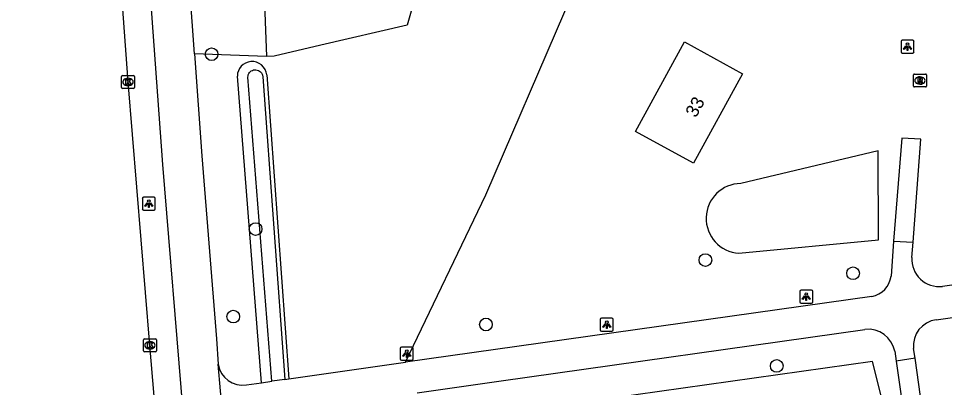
# Model space of a CAD drawing. Extents: x 159451 to 160663, y 388402 to 389723.
# Drawn here: x 159455.9 to 159527.4, y 389293.3 to 389321.7 of the extents above; entities that cross this region are included whole.
import ezdxf

# ---------------------------------------------------------------- set-up
doc = ezdxf.new("R2010")
doc.units = 0
for name, color, linetype in [('IMGEO_Boom', 7, 'Continuous'), ('IMGEO_Fietspad_gesloten', 7, 'Continuous'), ('IMGEO_Greppel_droge_sloot', 7, 'Continuous'), ('IMGEO_Kolk', 7, 'Continuous'), ('IMGEO_Lichtpunt', 7, 'Continuous'), ('IMGEO_Loofbos', 7, 'Continuous'), ('IMGEO_Meer_plas_ven_vijver', 7, 'Continuous'), ('IMGEO_Pand', 7, 'Continuous'), ('IMGEO_Pand_nummerreeks', 7, 'Continuous'), ('IMGEO_Rijbaan_lokaal_gesloten', 7, 'Continuous'), ('IMGEO_Rijbaan_regionaal_gesloten', 7, 'Continuous'), ('IMGEO_Rioolput', 7, 'Continuous')]:
    doc.layers.add(name, color=color, linetype=linetype)

msp = doc.modelspace()

# ---------------------------------------------------------------- linework, layer by layer
at = {"layer": 'IMGEO_Boom'}
for centre in [(159470.842, 389318.982), (159474.232, 389305.486), (159508.939, 389303.101), (159520.344, 389302.083), (159472.511, 389298.735), (159492.013, 389298.126), (159514.448, 389294.93)]:
    msp.add_circle(centre, 0.489, dxfattribs=at)
at = {"layer": 'IMGEO_Fietspad_gesloten'}
for points in [[(159469.519, 389319.015), (159468.808, 389329.001), (159467.416, 389348.979), (159465.554, 389376.915), (159464.112, 389404.118), (159462.376, 389437.214), (159460.98, 389466.613), (159459.958, 389496.642), (159459.465, 389512.981), (159459.166, 389522.863), (159459.08, 389525.773)], [(159455.942, 389525.002), (159456.038, 389522.126), (159456.372, 389512.313), (159456.916, 389496.35), (159457.955, 389465.071), (159459.294, 389436.93), (159461.071, 389403.687), (159462.508, 389376.402), (159464.342, 389348.5), (159465.649, 389329.916), (159467.063, 389310.472), (159468.609, 389291.384), (159470.151, 389272.51), (159471.683, 389255.143), (159473.293, 389238.955), (159476.115, 389210.723), (159476.688, 389204.954), (159478.244, 389191.231), (159479.81, 389178.066)], [(159469.519, 389319.015), (159470.079, 389311.141), (159471.221, 389297.013), (159471.345, 389295.068)]]:
    msp.add_lwpolyline(points, dxfattribs=at)
at = {"layer": 'IMGEO_Greppel_droge_sloot'}
msp.add_lwpolyline([(159475.498, 389293.751), (159473.642, 389317.216), (159473.65, 389317.307), (159473.674, 389317.398), (159473.713, 389317.483), (159473.764, 389317.561), (159473.828, 389317.63), (159473.902, 389317.688), (159473.985, 389317.732), (159474.073, 389317.763), (159474.163, 389317.779), (159474.265, 389317.779), (159474.364, 389317.761), (159474.459, 389317.727), (159474.546, 389317.676), (159474.624, 389317.611), (159474.688, 389317.534), (159474.739, 389317.447), (159474.773, 389317.352), (159474.794, 389317.233), (159476.493, 389293.892)], dxfattribs=at)
at = {"layer": 'IMGEO_Kolk'}
for p, q in [((159463.891, 389316.417), (159463.891, 389317.269)), ((159463.966, 389317.343), (159464.818, 389317.343)), ((159464.379, 389317.123), (159464.404, 389317.123)), ((159464.892, 389317.269), (159464.892, 389316.417)), ((159464.818, 389316.343), (159463.966, 389316.343)), ((159464.402, 389316.563), (159464.377, 389316.563)), ((159465.58, 389296.099), (159465.58, 389296.951)), ((159465.655, 389297.025), (159466.507, 389297.025)), ((159466.068, 389296.805), (159466.093, 389296.805)), ((159466.581, 389296.951), (159466.581, 389296.099)), ((159466.091, 389296.245), (159466.066, 389296.245)), ((159466.507, 389296.025), (159465.655, 389296.025))]:
    msp.add_line(p, q, dxfattribs=at)
for points in [[(159463.891, 389316.417), (159463.891, 389317.269)], [(159463.966, 389317.343), (159464.818, 389317.343)], [(159464.212, 389317.043), (159464.335, 389317.043), (159464.335, 389316.892), (159464.465, 389317.043), (159464.629, 389317.043), (159464.483, 389316.892), (159464.636, 389316.643), (159464.484, 389316.643), (159464.399, 389316.807), (159464.335, 389316.74), (159464.335, 389316.643), (159464.212, 389316.643), (159464.212, 389317.043)], [(159464.892, 389317.269), (159464.892, 389316.417)], [(159464.818, 389316.343), (159463.966, 389316.343)], [(159465.58, 389296.099), (159465.58, 389296.951)], [(159465.655, 389297.025), (159466.507, 389297.025)], [(159466.581, 389296.951), (159466.581, 389296.099)], [(159465.901, 389296.725), (159466.024, 389296.725), (159466.024, 389296.574), (159466.154, 389296.725), (159466.318, 389296.725), (159466.172, 389296.574), (159466.325, 389296.325), (159466.173, 389296.325), (159466.088, 389296.489), (159466.024, 389296.422), (159466.024, 389296.325), (159465.901, 389296.325), (159465.901, 389296.725)], [(159466.507, 389296.025), (159465.655, 389296.025)]]:
    msp.add_lwpolyline(points, dxfattribs=at)
for centre, start, end in [((159463.968, 389317.267), 91.55205, 178.44795), ((159463.968, 389317.267), 91.55205, 178.44795), ((159464.816, 389317.267), 1.55205, 88.44795), ((159464.816, 389317.267), 1.55205, 88.44795), ((159463.968, 389316.419), 181.55205, 268.44795), ((159463.968, 389316.419), 181.55205, 268.44795), ((159464.816, 389316.419), 271.55205, 358.44795), ((159464.816, 389316.419), 271.55205, 358.44795), ((159465.657, 389296.949), 91.55205, 178.44795), ((159465.657, 389296.949), 91.55205, 178.44795), ((159466.505, 389296.949), 1.55205, 88.44795), ((159466.505, 389296.949), 1.55205, 88.44795), ((159465.657, 389296.101), 181.55205, 268.44795), ((159465.657, 389296.101), 181.55205, 268.44795), ((159466.505, 389296.101), 271.55205, 358.44795), ((159466.505, 389296.101), 271.55205, 358.44795)]:
    msp.add_arc(centre, 0.0765, start, end, dxfattribs=at)
for centre, major_axis, ratio, start_param, end_param in [((159464.378, 389316.843), (-0.387, 0.002), 0.722429, 4.712389, 7.853982), ((159464.403, 389316.843), (-0.39, 0.002), 0.717154, 1.570796, 4.712389), ((159466.067, 389296.525), (-0.387, 0.002), 0.722429, 4.712389, 7.853982), ((159466.092, 389296.525), (-0.39, 0.002), 0.717154, 1.570796, 4.712389)]:
    msp.add_ellipse(centre, major_axis=major_axis, ratio=ratio, start_param=start_param, end_param=end_param, dxfattribs=at)
at = {"layer": 'IMGEO_Lichtpunt'}
for p, q in [((159524.044, 389319.966), (159524.044, 389319.159)), ((159524.044, 389319.966), (159524.044, 389319.159)), ((159524.946, 389320.061), (159524.138, 389320.061)), ((159524.946, 389320.061), (159524.138, 389320.061)), ((159525.04, 389319.159), (159525.04, 389319.966)), ((159525.04, 389319.159), (159525.04, 389319.966)), ((159524.138, 389319.065), (159524.946, 389319.065)), ((159524.138, 389319.065), (159524.946, 389319.065)), ((159465.496, 389307.856), (159465.496, 389307.049)), ((159465.496, 389307.856), (159465.496, 389307.049)), ((159466.398, 389307.951), (159465.59, 389307.951)), ((159466.398, 389307.951), (159465.59, 389307.951)), ((159466.492, 389307.049), (159466.492, 389307.856)), ((159466.492, 389307.049), (159466.492, 389307.856)), ((159465.59, 389306.955), (159466.398, 389306.955)), ((159465.59, 389306.955), (159466.398, 389306.955)), ((159516.229, 389300.684), (159516.229, 389299.877)), ((159516.229, 389300.684), (159516.229, 389299.877)), ((159517.131, 389300.779), (159516.323, 389300.779)), ((159517.131, 389300.779), (159516.323, 389300.779)), ((159517.225, 389299.877), (159517.225, 389300.684)), ((159517.225, 389299.877), (159517.225, 389300.684)), ((159516.323, 389299.783), (159517.131, 389299.783)), ((159516.323, 389299.783), (159517.131, 389299.783)), ((159500.834, 389298.511), (159500.834, 389297.704)), ((159500.834, 389298.511), (159500.834, 389297.704)), ((159501.736, 389298.606), (159500.928, 389298.606)), ((159501.736, 389298.606), (159500.928, 389298.606)), ((159501.83, 389297.704), (159501.83, 389298.511)), ((159501.83, 389297.704), (159501.83, 389298.511)), ((159500.928, 389297.61), (159501.736, 389297.61)), ((159500.928, 389297.61), (159501.736, 389297.61)), ((159485.399, 389296.277), (159485.399, 389295.47)), ((159485.399, 389296.277), (159485.399, 389295.47)), ((159486.301, 389296.372), (159485.493, 389296.372)), ((159486.301, 389296.372), (159485.493, 389296.372)), ((159486.395, 389295.47), (159486.395, 389296.277)), ((159486.395, 389295.47), (159486.395, 389296.277)), ((159485.493, 389295.376), (159486.301, 389295.376)), ((159485.493, 389295.376), (159486.301, 389295.376))]:
    msp.add_line(p, q, dxfattribs=at)
for points in [[(159524.418, 389319.63), (159524.457, 389319.602), (159524.269, 389319.34), (159524.231, 389319.367), (159524.418, 389319.63)], [(159524.63, 389319.602), (159524.668, 389319.629), (159524.855, 389319.367), (159524.816, 389319.339), (159524.63, 389319.602)], [(159524.52, 389319.582), (159524.567, 389319.582), (159524.567, 389319.26), (159524.52, 389319.26), (159524.52, 389319.582)], [(159465.87, 389307.52), (159465.909, 389307.492), (159465.721, 389307.23), (159465.683, 389307.257), (159465.87, 389307.52)], [(159465.972, 389307.472), (159466.019, 389307.472), (159466.019, 389307.15), (159465.972, 389307.15), (159465.972, 389307.472)], [(159466.082, 389307.492), (159466.12, 389307.519), (159466.307, 389307.257), (159466.268, 389307.229), (159466.082, 389307.492)], [(159516.603, 389300.348), (159516.642, 389300.32), (159516.454, 389300.058), (159516.416, 389300.085), (159516.603, 389300.348)], [(159516.815, 389300.32), (159516.853, 389300.347), (159517.04, 389300.085), (159517.001, 389300.057), (159516.815, 389300.32)], [(159516.705, 389300.3), (159516.752, 389300.3), (159516.752, 389299.978), (159516.705, 389299.978), (159516.705, 389300.3)], [(159501.208, 389298.175), (159501.247, 389298.147), (159501.059, 389297.885), (159501.021, 389297.912), (159501.208, 389298.175)], [(159501.31, 389298.127), (159501.357, 389298.127), (159501.357, 389297.805), (159501.31, 389297.805), (159501.31, 389298.127)], [(159501.42, 389298.147), (159501.458, 389298.174), (159501.645, 389297.912), (159501.606, 389297.884), (159501.42, 389298.147)], [(159485.773, 389295.941), (159485.812, 389295.913), (159485.624, 389295.651), (159485.586, 389295.678), (159485.773, 389295.941)], [(159485.875, 389295.893), (159485.922, 389295.893), (159485.922, 389295.571), (159485.875, 389295.571), (159485.875, 389295.893)], [(159485.985, 389295.913), (159486.023, 389295.94), (159486.21, 389295.678), (159486.171, 389295.65), (159485.985, 389295.913)]]:
    msp.add_lwpolyline(points, dxfattribs=at)
for centre in [(159524.543, 389319.764), (159465.995, 389307.654), (159516.728, 389300.482), (159501.333, 389298.309), (159485.898, 389296.075)]:
    msp.add_circle(centre, 0.0994, dxfattribs=at)
for centre, start, end in [((159524.138, 389319.966), 90, 180), ((159524.138, 389319.966), 90, 180), ((159524.946, 389319.966), 0, 90), ((159524.946, 389319.966), 0, 90), ((159524.138, 389319.159), 180, 270), ((159524.138, 389319.159), 180, 270), ((159524.946, 389319.159), 270, 0), ((159524.946, 389319.159), 270, 360), ((159465.59, 389307.856), 90, 180), ((159465.59, 389307.856), 90, 180), ((159466.398, 389307.856), 0, 90), ((159466.398, 389307.856), 0, 90), ((159465.59, 389307.049), 180, 270), ((159465.59, 389307.049), 180, 270), ((159466.398, 389307.049), 270, 0), ((159466.398, 389307.049), 270, 360), ((159516.323, 389300.684), 90, 180), ((159516.323, 389300.684), 90, 180), ((159517.131, 389300.684), 0, 90), ((159517.131, 389300.684), 0, 90), ((159516.323, 389299.877), 180, 270), ((159516.323, 389299.877), 180, 270), ((159517.131, 389299.877), 270, 0), ((159517.131, 389299.877), 270, 360), ((159500.928, 389298.511), 90, 180), ((159500.928, 389298.511), 90, 180), ((159501.736, 389298.511), 0, 90), ((159501.736, 389298.511), 0, 90), ((159500.928, 389297.704), 180, 270), ((159500.928, 389297.704), 180, 270), ((159501.736, 389297.704), 270, 0), ((159501.736, 389297.704), 270, 360), ((159485.493, 389296.277), 90, 180), ((159485.493, 389296.277), 90, 180), ((159486.301, 389296.277), 0, 90), ((159486.301, 389296.277), 0, 90), ((159485.493, 389295.47), 180, 270), ((159485.493, 389295.47), 180, 270), ((159486.301, 389295.47), 270, 0), ((159486.301, 389295.47), 270, 360)]:
    msp.add_arc(centre, 0.0946, start, end, dxfattribs=at)
at = {"layer": 'IMGEO_Loofbos'}
for points in [[(159467.537, 389516.526), (159475.08, 389318.792)], [(159485.81, 389295.214), (159491.991, 389308.123), (159504.183, 389336.444), (159514.866, 389357.937), (159544.814, 389411.565), (159556.465, 389431.123), (159566.644, 389445.466), (159585.18, 389466.829), (159590.702, 389478.946), (159594.278, 389488.578), (159596.128, 389493.71), (159598.507, 389500.31)], [(159488.618, 389330.562), (159485.934, 389321.215), (159479.261, 389319.665), (159475.672, 389318.831), (159475.08, 389318.792)], [(159475.08, 389318.792), (159469.519, 389319.015)], [(159474.699, 389293.638), (159472.828, 389317.295)], [(159475.093, 389317.376), (159476.799, 389293.936)]]:
    msp.add_lwpolyline(points, dxfattribs=at)
for centre, radius, start, end in [((159473.962, 389317.28), 1.134, 95.11751, 179.25491), ((159473.96, 389317.276), 1.138, 5.01984, 94.96765)]:
    msp.add_arc(centre, radius, start, end, dxfattribs=at)
at = {"layer": 'IMGEO_Meer_plas_ven_vijver'}
for points in [[(159522.313, 389304.654), (159522.275, 389311.536), (159511.676, 389309.006)], [(159511.527, 389303.624), (159522.313, 389304.654)], [(159521.069, 389241.65), (159518.659, 389246.126), (159517.22, 389247.851), (159515.886, 389256.055), (159514.744, 389257.84), (159511.894, 389259.653), (159504.61, 389284.226), (159509.011, 389285.515), (159523.74, 389287.733), (159521.85, 389295.267), (159496.278, 389291.663), (159494.831, 389290.177), (159494.743, 389289.39), (159511.127, 389249.352), (159515.724, 389239.283), (159521.069, 389241.65)]]:
    msp.add_lwpolyline(points, dxfattribs=at)
msp.add_arc((159511.697, 389306.312), 2.694, 90.44666, 266.3817, dxfattribs=at)
at = {"layer": 'IMGEO_Pand'}
msp.add_lwpolyline([(159511.812, 389317.468), (159508.032, 389310.567), (159503.562, 389313.015), (159507.34, 389319.922), (159511.812, 389317.468)], dxfattribs=at)
at = {"layer": 'IMGEO_Rijbaan_lokaal_gesloten'}
for points in [[(159524.968, 389304.47), (159525.556, 389312.414), (159524.108, 389312.501), (159523.448, 389304.552)], [(159558.3, 389305.469), (159527.236, 389301.062)], [(159523.448, 389304.552), (159523.268, 389301.867)], [(159523.448, 389304.552), (159524.968, 389304.47)], [(159524.866, 389303.302), (159524.968, 389304.47)], [(159526.743, 389298.498), (159558.75, 389303.048)], [(159521.777, 389300.297), (159492.759, 389296.199), (159485.81, 389295.214)], [(159486.712, 389292.863), (159493.172, 389293.777), (159521.25, 389297.74)], [(159523.555, 389296.061), (159523.669, 389295.299)], [(159525.136, 389295.518), (159525.003, 389296.267)], [(159525.136, 389295.518), (159523.669, 389295.299)], [(159526.226, 389287.573), (159525.136, 389295.518)], [(159471.882, 389288.893), (159471.345, 389295.068)], [(159476.799, 389293.936), (159485.81, 389295.214)], [(159523.669, 389295.299), (159524.796, 389287.372)], [(159476.493, 389293.892), (159476.799, 389293.936)], [(159473.535, 389293.473), (159474.699, 389293.638)], [(159474.699, 389293.638), (159475.498, 389293.751)], [(159476.493, 389293.892), (159475.498, 389293.751)]]:
    msp.add_lwpolyline(points, dxfattribs=at)
for centre, radius, start, end in [((159526.998, 389303.184), 2.135, 176.82421, 276.40637), ((159521.497, 389302.056), 1.781, 279.04609, 353.91069), ((159527.037, 389296.475), 2.044, 98.26043, 185.83686), ((159521.518, 389295.687), 2.071, 10.41627, 97.44331), ((159473.24, 389295.369), 1.919, 189.02687, 278.84065)]:
    msp.add_arc(centre, radius, start, end, dxfattribs=at)
at = {"layer": 'IMGEO_Rijbaan_regionaal_gesloten'}
msp.add_lwpolyline([(159475.213, 389199.409), (159473.713, 389213.767), (159472.153, 389229.121), (159470.673, 389244.477), (159469.405, 389257.836), (159468.669, 389266.005), (159467.728, 389277.179), (159466.081, 389296.525), (159464.392, 389316.843), (159462.91, 389337.218), (159462.193, 389348.076), (159461.584, 389357.574), (159460.45, 389376.955), (159459.237, 389397.341)], dxfattribs=at)
at = {"layer": 'IMGEO_Rioolput'}
for p, q in [((159524.994, 389316.525), (159524.994, 389317.377)), ((159525.069, 389317.451), (159525.921, 389317.451)), ((159525.482, 389317.231), (159525.507, 389317.231)), ((159525.995, 389317.377), (159525.995, 389316.525)), ((159525.921, 389316.451), (159525.069, 389316.451)), ((159525.505, 389316.671), (159525.48, 389316.671))]:
    msp.add_line(p, q, dxfattribs=at)
for points in [[(159524.994, 389316.525), (159524.994, 389317.377)], [(159525.069, 389317.451), (159525.921, 389317.451)], [(159525.583, 389317.149), (159525.331, 389317.151), (159525.331, 389316.751)], [(159525.331, 389316.751), (159525.455, 389316.751), (159525.455, 389316.913), (159525.466, 389316.913)], [(159525.509, 389317.07), (159525.455, 389317.07), (159525.455, 389316.989)], [(159525.455, 389316.989), (159525.507, 389316.989)], [(159525.513, 389316.884), (159525.584, 389316.751), (159525.724, 389316.751), (159525.659, 389316.877)], [(159525.995, 389317.377), (159525.995, 389316.525)], [(159525.921, 389316.451), (159525.069, 389316.451)]]:
    msp.add_lwpolyline(points, dxfattribs=at)
for centre, radius, start, end in [((159525.071, 389317.375), 0.0765, 91.55205, 178.44795), ((159525.071, 389317.375), 0.0765, 91.55205, 178.44795), ((159525.465, 389316.86), 0.0533, 26.02933, 88.69889), ((159525.491, 389317.178), 0.19, 274.7715, 282.96867), ((159525.515, 389316.974), 0.0964, 77.00612, 93.18647), ((159525.529, 389317.031), 0.0378, 276.66336, 79.67722), ((159525.582, 389317.039), 0.109, 350.36119, 89.41601), ((159525.58, 389317.039), 0.112, 277.58423, 350.98172), ((159525.564, 389316.824), 0.108, 29.51342, 73.79051), ((159525.919, 389317.375), 0.0765, 1.55205, 88.44795), ((159525.919, 389317.375), 0.0765, 1.55205, 88.44795), ((159525.071, 389316.527), 0.0765, 181.55205, 268.44795), ((159525.071, 389316.527), 0.0765, 181.55205, 268.44795), ((159525.919, 389316.527), 0.0765, 271.55205, 358.44795), ((159525.919, 389316.527), 0.0765, 271.55205, 358.44795)]:
    msp.add_arc(centre, radius, start, end, dxfattribs=at)
for centre, major_axis, ratio, start_param, end_param in [((159525.481, 389316.951), (-0.387, 0.002), 0.722429, 4.712389, 7.853982), ((159525.506, 389316.951), (-0.39, 0.002), 0.717154, 1.570796, 4.712389)]:
    msp.add_ellipse(centre, major_axis=major_axis, ratio=ratio, start_param=start_param, end_param=end_param, dxfattribs=at)

# ---------------------------------------------------------------- texts
at = {"layer": 'IMGEO_Pand_nummerreeks'}
msp.add_text('33', height=1, rotation=61.2893, dxfattribs=at).set_placement((159508.218, 389314.03))

doc.saveas('drawing.dxf')
